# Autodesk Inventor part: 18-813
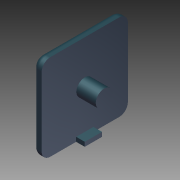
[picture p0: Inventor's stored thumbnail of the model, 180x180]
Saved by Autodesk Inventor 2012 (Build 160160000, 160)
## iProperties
Created: 2006-02
Part Number: 18-813
Material: Glass Filled Nylon
Document SubType Name: Modeling
Designer: Autodesk, Inc.
Manufacturer: Standard
Standards Organization: Custom
Description: END CAP, 40 SERIES, 40x40
Catalog Web Link: http://www.parker.com/ead/cm1.asp?cmid=809
Vendor: PARKER IPS
Mass: 7.50143 g
Surface Area: 39.1851 cm^2
Volume: 6.63843 cm^3
Density: 1.13 g/cm^3
Author: Autodesk, Inc.
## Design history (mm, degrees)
sketch "Sketch1"
  geometry: L1 (-20, 20)-(20, 20); L2 (20, 20)-(20, -20); L3 (20, -20)-(-20, -20); L4 (-20, -20)-(-20, 20); 3 further points
  constraints: 8 end point, 2 midpoint, 2 parallel, 1 horizontal, 1 horizontal alignment, 1 perpendicular, 1 vertical alignment
  dimensions: "DimA" = 40 distance of L1.start L1.end; "DimB" = 40 distance of L3.end L1.start
extrude "Rectangluar End Cap" new body sketch "Sketch1" distance "d2" = 4; taper "d3" = 0 deg
sketch "Sketch6"
  geometry: L1 (-20, -20)-(-20, 20) reference; L2 (20, -20)-(-20, -20) reference; C1 r 3.9 at (0, 0)
  constraints: 1 centre point
  dimensions: "d37" = 20 distance from line of C1.centre L1; "d38" = 20 distance from line of C1.centre L2; "d39" = 7.8 diameter of C1
extrude "Standard Post" join sketch "Sketch6" distance "d40" = 13; taper "d41" = 0 deg
hole "Secure End Cap" sketch "Sketch6" diameter "d48" = 4.5; stored, may be unused: countersink angle "d52" = 90 deg, drill point angle "d54" = 118 deg; dims "d49" = 6, "d50" = 9.4, "d51" = 2, "d53" = 8
pattern_linear "Rectangular Pattern3"
sketch "Sketch7"
  geometry: L1 (-20, -20)-(20, -20) reference; L2 (-4, -20)-(4, -20); L3 (4, -20)-(4, -18); L4 (4, -18)-(-4, -18); L5 (-4, -18)-(-4, -20); L6 (0, -18)-(0, -20); 1 further point
  constraints: 10 end point, 2 midpoint, 2 parallel, 2 point on line, 1 horizontal, 1 perpendicular
  dimensions: "d55" = 2 distance of L4.end L2.start; "d56" = 8 distance of L3.end L4.end
extrude "40x40 Orientation Tab" join sketch "Sketch7" distance "d57" = 4; taper "d58" = 0 deg
fillet "Fillet5" dims "d59" = 4
fillet "Fillet6" dims "d60" = 2.5
body "Solid1"
